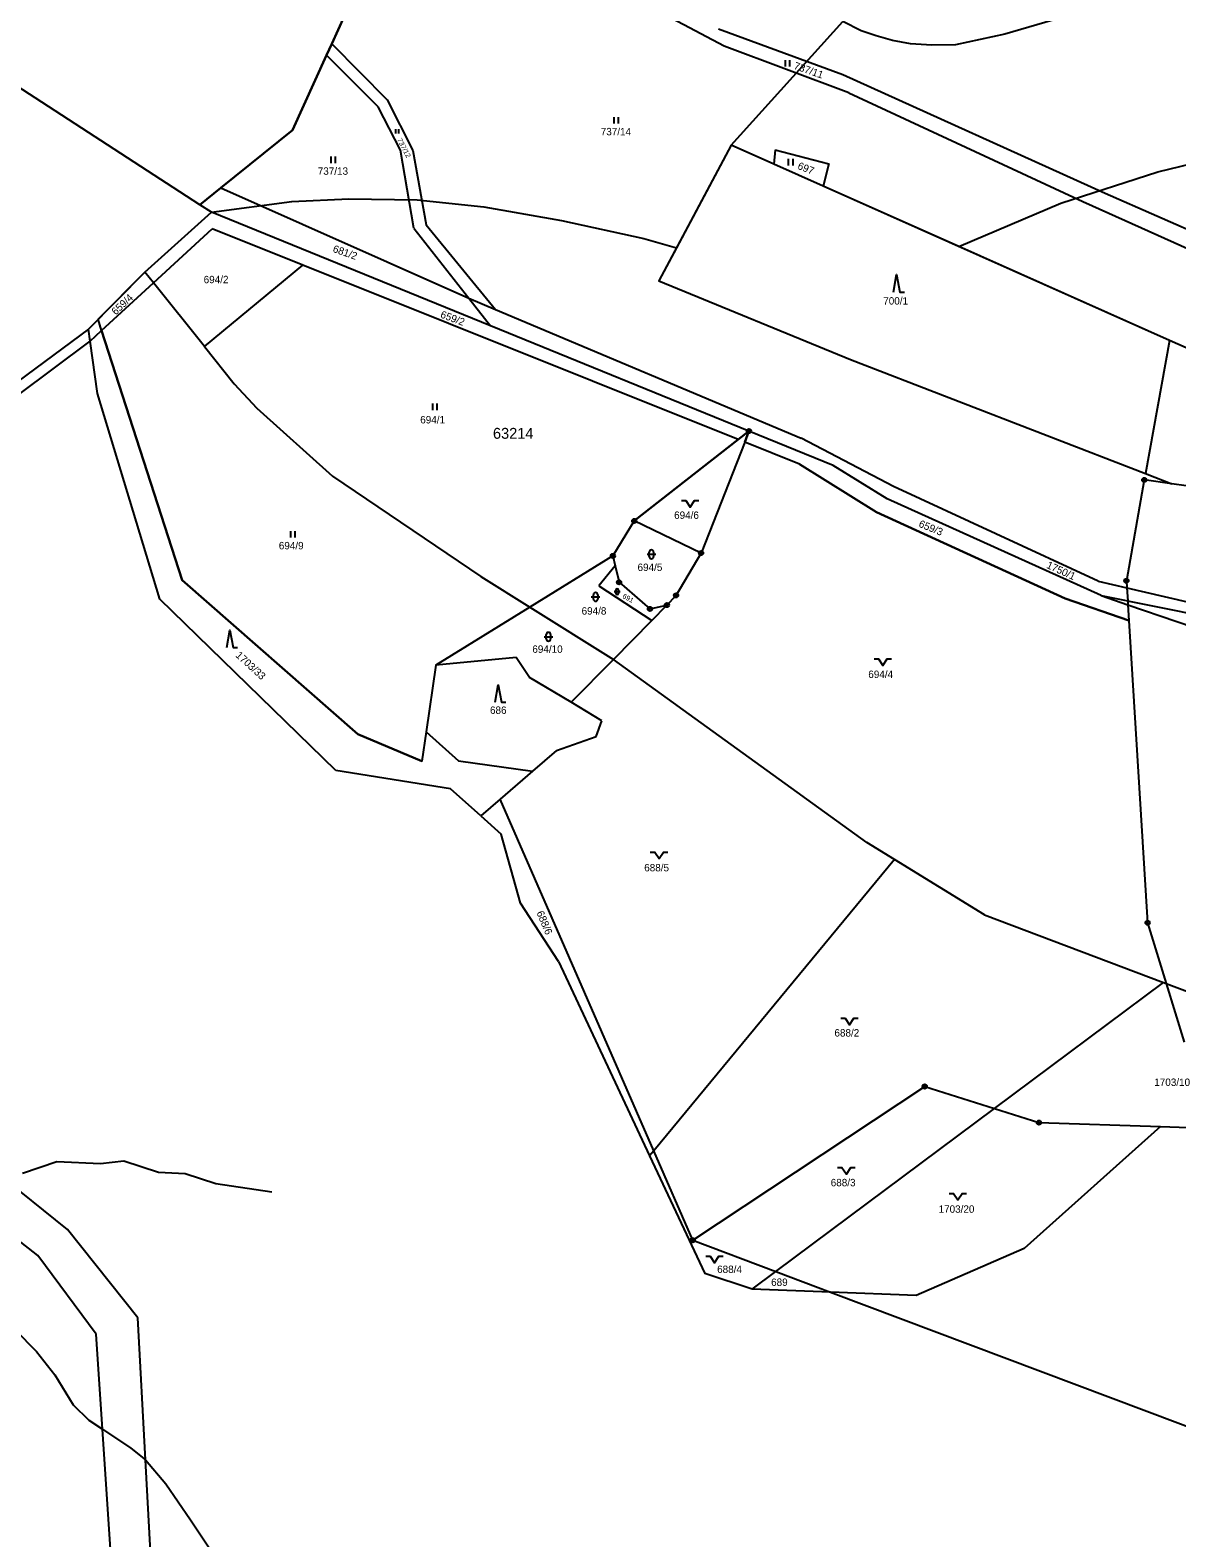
# Model space of a CAD drawing. Extents: x -546762 to -540209, y -1046851 to -1035694.
# Drawn here: x -543953 to -543689.8, y -1042773.8 to -1042427.6 of the extents above; entities that cross this region are included whole.
import ezdxf

# ---------------------------------------------------------------- set-up
doc = ezdxf.new("R2010")
doc.units = 0
for name, color, linetype in [('Vrstva 1', 7, 'Continuous'), ('Vrstva 18', 7, 'Continuous'), ('Vrstva 24', 7, 'Continuous'), ('Vrstva 25', 7, 'Continuous'), ('Vrstva 4', 7, 'Continuous'), ('Vrstva 52', 7, 'Continuous'), ('Vrstva 53', 7, 'Continuous'), ('Vrstva 6', 7, 'Continuous')]:
    doc.layers.add(name, color=color, linetype=linetype)

msp = doc.modelspace()

# ---------------------------------------------------------------- linework, layer by layer
at = {"layer": 'Vrstva 1'}
msp.add_line((-543914, -1042467.7), (-543986.75, -1042420.55), dxfattribs=at)
for points in [[(-543880.86, -1042424.34), (-543883.76, -1042430.75)], [(-543884.95, -1042433.37), (-543892.75, -1042450.56)], [(-543883.76, -1042430.75), (-543884.95, -1042433.37)], [(-543892.75, -1042450.56), (-543909.21, -1042463.84)], [(-543792.12, -1042454.05), (-543808.73, -1042485.17)], [(-543782.33, -1042458.41), (-543792.12, -1042454.05)], [(-543770.99, -1042463.46), (-543782.33, -1042458.41)], [(-543909.21, -1042463.84), (-543914, -1042467.7)], [(-543909.21, -1042463.84), (-543852.31, -1042489.17)], [(-543691.54, -1042498.84), (-543770.99, -1042463.46)], [(-543911.35, -1042469.41), (-543914, -1042467.7)], [(-543926.67, -1042483.2), (-543911.35, -1042469.41)], [(-543847.36, -1042495.5), (-543911.35, -1042469.41)], [(-543924.65, -1042485.6), (-543911.22, -1042473.23)], [(-543890.39, -1042481.58), (-543911.22, -1042473.23)], [(-543912.98, -1042500.25), (-543890.39, -1042481.58)], [(-543790.47, -1042521.6), (-543890.39, -1042481.58)], [(-543939.58, -1042496.26), (-543926.67, -1042483.2)], [(-543936.6, -1042496.61), (-543924.65, -1042485.6)], [(-543912.98, -1042500.25), (-543924.65, -1042485.6)], [(-543808.73, -1042485.17), (-543764.69, -1042503.24)], [(-543852.31, -1042489.17), (-543846.15, -1042491.77)], [(-543852.31, -1042489.17), (-543847.36, -1042495.5)], [(-543846.15, -1042491.77), (-543776.05, -1042521.32)], [(-543939.58, -1042496.26), (-544006.86, -1042546.1)], [(-543788.02, -1042519.68), (-543847.36, -1042495.5)], [(-544013.86, -1042554.81), (-543939.22, -1042499.03)], [(-543939.22, -1042499.03), (-543936.6, -1042496.61)], [(-543936.6, -1042496.61), (-543918.07, -1042553.94)], [(-543691.54, -1042498.84), (-543697.04, -1042529.44)], [(-543643.01, -1042520.26), (-543691.54, -1042498.84)], [(-543764.69, -1042503.24), (-543697.04, -1042529.44)], [(-543790.47, -1042521.6), (-543788.02, -1042519.68)], [(-543788.02, -1042519.68), (-543789, -1042522.19)], [(-543768.69, -1042527.56), (-543788.02, -1042519.68)], [(-543814.33, -1042540.29), (-543790.47, -1042521.6)], [(-543789, -1042522.19), (-543799, -1042547.69)], [(-543776.4, -1042527.24), (-543789, -1042522.19)], [(-543754.86, -1042532.43), (-543776.05, -1042521.32)], [(-543776.4, -1042527.24), (-543758.78, -1042538.26)], [(-543756.29, -1042535.23), (-543768.69, -1042527.56)], [(-543697.3, -1042530.9), (-543701.4, -1042554.03)], [(-543691.01, -1042531.78), (-543697.3, -1042530.9)], [(-543697.04, -1042529.44), (-543691.01, -1042531.78)], [(-543707.88, -1042554.12), (-543754.86, -1042532.43)], [(-543671.28, -1042534.53), (-543691.01, -1042531.78)], [(-543707.2, -1042557.44), (-543756.29, -1042535.23)], [(-543814.33, -1042540.29), (-543819.25, -1042548.35)], [(-543799, -1042547.69), (-543814.33, -1042540.29)], [(-543758.78, -1042538.26), (-543715.46, -1042558.09)], [(-543819.25, -1042548.35), (-543838.28, -1042560.08)], [(-543819.25, -1042548.35), (-543818.71, -1042550.63)], [(-543804.74, -1042557.39), (-543799, -1042547.69)], [(-543818.71, -1042550.63), (-543817.82, -1042554.38)], [(-543918.07, -1042553.94), (-543877.78, -1042589.27)], [(-543817.82, -1042554.38), (-543810.73, -1042560.5)], [(-543707.88, -1042554.12), (-543701.3, -1042555.64)], [(-543701.4, -1042554.03), (-543701.3, -1042555.64)], [(-543806.84, -1042559.61), (-543804.74, -1042557.39)], [(-543715.46, -1042558.09), (-543700.84, -1042563.16)], [(-543707.2, -1042557.44), (-543701.06, -1042559.54)], [(-543707.2, -1042557.44), (-543682.5, -1042562.38)], [(-543701.3, -1042555.64), (-543683.15, -1042559.84)], [(-543838.28, -1042560.08), (-543859.89, -1042573.41)], [(-543810.73, -1042560.5), (-543806.84, -1042559.61)], [(-543810.34, -1042563.16), (-543806.84, -1042559.61)], [(-543701.06, -1042559.54), (-543644.86, -1042578.71)], [(-543701.06, -1042559.54), (-543700.84, -1042563.16)], [(-543819.11, -1042572.08), (-543810.34, -1042563.16)], [(-543700.84, -1042563.16), (-543696.55, -1042632.54)], [(-543841.41, -1042571.65), (-543859.89, -1042573.41)], [(-543838.38, -1042576.23), (-543841.41, -1042571.65)], [(-543828.82, -1042581.95), (-543819.11, -1042572.08)], [(-543760.97, -1042614.11), (-543819.11, -1042572.08)], [(-543859.89, -1042573.41), (-543862.09, -1042588.69)], [(-543828.82, -1042581.95), (-543838.38, -1042576.23)], [(-543821.74, -1042586.18), (-543828.82, -1042581.95)], [(-543823.08, -1042589.77), (-543821.74, -1042586.18)], [(-543877.78, -1042589.27), (-543863.06, -1042595.46)], [(-543862.09, -1042588.69), (-543863.06, -1042595.46)], [(-543832.18, -1042593.02), (-543823.08, -1042589.77)], [(-543832.18, -1042593.02), (-543837.67, -1042597.76)], [(-543837.67, -1042597.76), (-543845.09, -1042604.16)], [(-543845.09, -1042604.16), (-543849.56, -1042608.02)], [(-543809.86, -1042684.9), (-543845.09, -1042604.16)], [(-543849.56, -1042608.02), (-543844.9, -1042612.18)], [(-543840.45, -1042628.07), (-543844.9, -1042612.18)], [(-543754.62, -1042618.03), (-543760.97, -1042614.11)], [(-543754.62, -1042618.03), (-543809.86, -1042684.9)], [(-543734, -1042630.76), (-543754.62, -1042618.03)], [(-543831.74, -1042641.43), (-543840.45, -1042628.07)], [(-543734, -1042630.76), (-543692.88, -1042646.27)], [(-543696.55, -1042632.54), (-543692.29, -1042646.49)], [(-543831.74, -1042641.43), (-543810.83, -1042686.07)], [(-543731.68, -1042675.22), (-543692.88, -1042646.27)], [(-543692.88, -1042646.27), (-543692.29, -1042646.49)], [(-543692.29, -1042646.49), (-543663.02, -1042657.52)], [(-543692.29, -1042646.49), (-543688.16, -1042659.98)], [(-543800.9, -1042705.44), (-543747.67, -1042670.15)], [(-543747.67, -1042670.15), (-543731.68, -1042675.22)], [(-543781.83, -1042712.63), (-543731.68, -1042675.22)], [(-543731.68, -1042675.22), (-543721.47, -1042678.45)], [(-543693.55, -1042679.34), (-543724.87, -1042707.38)], [(-543721.47, -1042678.45), (-543693.55, -1042679.34)], [(-543693.55, -1042679.34), (-543682.85, -1042679.68)], [(-543809.86, -1042684.9), (-543810.83, -1042686.07)], [(-543810.83, -1042686.07), (-543798.17, -1042713.1)], [(-543800.9, -1042705.44), (-543809.86, -1042684.9)], [(-543944.41, -1042703), (-543960.57, -1042690)], [(-543951.18, -1042708.96), (-543973.27, -1042691.69)], [(-543928.23, -1042723.28), (-543944.41, -1042703)], [(-543800.9, -1042705.44), (-543781.83, -1042712.63)], [(-543724.87, -1042707.38), (-543749.65, -1042718.1)], [(-543937.83, -1042726.98), (-543951.18, -1042708.96)], [(-543787.25, -1042716.67), (-543798.17, -1042713.1)], [(-543787.25, -1042716.67), (-543781.83, -1042712.63)], [(-543781.83, -1042712.63), (-543769.3, -1042717.35)], [(-543769.3, -1042717.35), (-543656.9, -1042759.71)], [(-543749.65, -1042718.1), (-543769.3, -1042717.35)], [(-543926.46, -1042755.84), (-543928.23, -1042723.28)], [(-543936.37, -1042748.84), (-543937.83, -1042726.98)], [(-543930.94, -1042830.38), (-543936.37, -1042748.84)], [(-543922.81, -1042823.23), (-543926.46, -1042755.84)]]:
    msp.add_lwpolyline(points, dxfattribs=at)
at = {"layer": 'Vrstva 24'}
for centre, radius in [((-543788.02, -1042519.68), 0.5), ((-543788.02, -1042519.68), 0.1), ((-543697.3, -1042530.9), 0.5), ((-543697.3, -1042530.9), 0.1), ((-543814.33, -1042540.29), 0.5), ((-543814.33, -1042540.29), 0.1), ((-543819.25, -1042548.35), 0.5), ((-543819.25, -1042548.35), 0.1), ((-543799, -1042547.69), 0.5), ((-543799, -1042547.69), 0.1), ((-543817.82, -1042554.38), 0.5), ((-543817.82, -1042554.38), 0.1), ((-543701.4, -1042554.03), 0.5), ((-543701.4, -1042554.03), 0.1), ((-543804.74, -1042557.39), 0.5), ((-543804.74, -1042557.39), 0.1), ((-543810.73, -1042560.5), 0.5), ((-543810.73, -1042560.5), 0.1), ((-543806.84, -1042559.61), 0.5), ((-543806.84, -1042559.61), 0.1), ((-543696.55, -1042632.54), 0.5), ((-543696.55, -1042632.54), 0.1), ((-543747.67, -1042670.15), 0.5), ((-543747.67, -1042670.15), 0.1), ((-543721.47, -1042678.45), 0.5), ((-543721.47, -1042678.45), 0.1), ((-543800.9, -1042705.44), 0.5), ((-543800.9, -1042705.44), 0.1)]:
    msp.add_circle(centre, radius, dxfattribs=at)
at = {"layer": 'Vrstva 25'}
for p, q in [((-543779.63, -1042435.99), (-543779.63, -1042434.49)), ((-543778.63, -1042435.99), (-543778.63, -1042434.49)), ((-543818.94, -1042449.07), (-543818.94, -1042447.57)), ((-543817.94, -1042449.07), (-543817.94, -1042447.57)), ((-543869.02, -1042451.37), (-543869.02, -1042450.36)), ((-543868.34, -1042451.37), (-543868.34, -1042450.36)), ((-543883.88, -1042458.13), (-543883.88, -1042456.63)), ((-543882.88, -1042458.13), (-543882.88, -1042456.63)), ((-543778.91, -1042458.67), (-543778.91, -1042457.17)), ((-543777.91, -1042458.67), (-543777.91, -1042457.17)), ((-543860.53, -1042514.86), (-543860.53, -1042513.36)), ((-543859.53, -1042514.86), (-543859.53, -1042513.36)), ((-543893.16, -1042544.12), (-543893.16, -1042542.62)), ((-543892.16, -1042544.12), (-543892.16, -1042542.62)), ((-543811.41, -1042547.97), (-543809.41, -1042547.97)), ((-543810.91, -1042548.47), (-543810.91, -1042547.47)), ((-543809.91, -1042547.47), (-543809.91, -1042548.47)), ((-543824.22, -1042557.74), (-543822.22, -1042557.74)), ((-543823.72, -1042558.24), (-543823.72, -1042557.24)), ((-543822.72, -1042557.24), (-543822.72, -1042558.24)), ((-543818.92, -1042556.54), (-543817.58, -1042556.54)), ((-543818.58, -1042556.88), (-543818.58, -1042556.21)), ((-543817.92, -1042556.21), (-543817.92, -1042556.88)), ((-543835.02, -1042566.88), (-543833.02, -1042566.88)), ((-543834.52, -1042567.38), (-543834.52, -1042566.38)), ((-543833.52, -1042566.38), (-543833.52, -1042567.38))]:
    msp.add_line(p, q, dxfattribs=at)
for points in [[(-543754.86, -1042487.75), (-543754.16, -1042483.75), (-543753.36, -1042487.75), (-543752.36, -1042487.75)], [(-543803.5, -1042535.63), (-543802.5, -1042535.63), (-543801.5, -1042537.13), (-543800.5, -1042535.63), (-543799.5, -1042535.63)], [(-543907.86, -1042569.35), (-543907.16, -1042565.35), (-543906.36, -1042569.35), (-543905.36, -1042569.35)], [(-543759.28, -1042571.98), (-543758.28, -1042571.98), (-543757.28, -1042573.48), (-543756.28, -1042571.98), (-543755.28, -1042571.98)], [(-543846.29, -1042581.9), (-543845.59, -1042577.9), (-543844.79, -1042581.9), (-543843.79, -1042581.9)], [(-543810.65, -1042616.32), (-543809.65, -1042616.32), (-543808.65, -1042617.82), (-543807.65, -1042616.32), (-543806.65, -1042616.32)], [(-543766.94, -1042654.48), (-543765.94, -1042654.48), (-543764.94, -1042655.98), (-543763.94, -1042654.48), (-543762.94, -1042654.48)], [(-543767.67, -1042688.74), (-543766.67, -1042688.74), (-543765.67, -1042690.24), (-543764.67, -1042688.74), (-543763.67, -1042688.74)], [(-543742.11, -1042694.7), (-543741.11, -1042694.7), (-543740.11, -1042696.2), (-543739.11, -1042694.7), (-543738.11, -1042694.7)], [(-543797.94, -1042709.13), (-543796.94, -1042709.13), (-543795.94, -1042710.63), (-543794.94, -1042709.13), (-543793.94, -1042709.13)]]:
    msp.add_lwpolyline(points, dxfattribs=at)
for centre, radius, start, end in [((-543810.41, -1042547.47), 0.5, 0, 180), ((-543810.41, -1042548.47), 0.5, 180, 0), ((-543823.22, -1042557.24), 0.5, 0, 180), ((-543823.22, -1042558.24), 0.5, 180, 0), ((-543818.25, -1042556.21), 0.335, 0, 180), ((-543818.25, -1042556.88), 0.335, 180, 0), ((-543834.02, -1042566.38), 0.5, 0, 180), ((-543834.02, -1042567.38), 0.5, 180, 0)]:
    msp.add_arc(centre, radius, start, end, dxfattribs=at)
at = {"layer": 'Vrstva 4'}
for points in [[(-543954.69, -1042690.05), (-543946.87, -1042687.34)], [(-543946.87, -1042687.34), (-543936.83, -1042687.84)], [(-543936.83, -1042687.84), (-543931.45, -1042687.23)], [(-543931.45, -1042687.23), (-543923.53, -1042689.82)], [(-543923.53, -1042689.82), (-543917.38, -1042690.11)], [(-543917.38, -1042690.11), (-543910.35, -1042692.42)], [(-543910.35, -1042692.42), (-543897.5, -1042694.37)], [(-543956.37, -1042726.05), (-543951.51, -1042730.98)], [(-543951.51, -1042730.98), (-543947.33, -1042736.38)], [(-543947.33, -1042736.38), (-543943.06, -1042743.26)], [(-543943.06, -1042743.26), (-543939.49, -1042746.78)], [(-543939.49, -1042746.78), (-543936.37, -1042748.84)], [(-543936.37, -1042748.84), (-543929.85, -1042753.16)], [(-543929.85, -1042753.16), (-543926.46, -1042755.84)], [(-543926.46, -1042755.84), (-543921.82, -1042761.37)], [(-543921.82, -1042761.37), (-543916.14, -1042769.65)], [(-543916.14, -1042769.65), (-543910.63, -1042777.9)]]:
    msp.add_lwpolyline(points, dxfattribs=at)
at = {"layer": 'Vrstva 52'}
for points in [[(-543911.35, -1042469.41), (-543914, -1042467.7), (-543909.21, -1042463.84), (-543892.75, -1042450.56), (-543884.95, -1042433.37), (-543883.76, -1042430.75), (-543880.86, -1042424.34), (-543864.22, -1042393.81), (-543874.9, -1042389.04)], [(-543792.12, -1042454.05), (-543766.5, -1042425.67)], [(-543716.49, -1042424.8), (-543729.32, -1042428.56), (-543740.59, -1042430.98), (-543746.09, -1042431.07), (-543750.93, -1042430.79), (-543755.09, -1042430.03), (-543758.82, -1042428.92), (-543762.28, -1042427.75), (-543766.5, -1042425.67)], [(-543739.84, -1042477.33), (-543716.42, -1042467.37), (-543694.17, -1042460.16), (-543673.4, -1042455.07), (-543651.36, -1042451.67), (-543626.13, -1042450.4), (-543604.73, -1042450.61), (-543582.48, -1042451.46), (-543555.56, -1042452.31), (-543534.58, -1042453.58), (-543520.38, -1042453.58), (-543509.36, -1042452.52), (-543500.76, -1042451.67), (-543493.37, -1042450.71), (-543489.01, -1042450.46)], [(-543792.12, -1042454.05), (-543804.68, -1042477.58)], [(-543739.84, -1042477.33), (-543770.99, -1042463.46), (-543782.33, -1042458.41), (-543792.12, -1042454.05)], [(-543911.35, -1042469.41), (-543892.94, -1042466.97), (-543879.86, -1042466.37), (-543864.12, -1042466.61)], [(-543864.12, -1042466.61), (-543848.86, -1042468.18), (-543831.06, -1042471.33), (-543812.16, -1042475.45), (-543804.68, -1042477.58)], [(-543804.68, -1042477.58), (-543808.73, -1042485.17), (-543764.69, -1042503.24), (-543697.04, -1042529.44), (-543691.01, -1042531.78), (-543697.3, -1042530.9), (-543701.4, -1042554.03), (-543701.3, -1042555.64), (-543701.11, -1042558.66), (-543701.06, -1042559.54), (-543700.84, -1042563.16), (-543715.46, -1042558.09), (-543758.78, -1042538.26), (-543776.4, -1042527.24), (-543789, -1042522.19), (-543788.02, -1042519.68), (-543790.47, -1042521.6), (-543814.33, -1042540.29), (-543819.25, -1042548.35), (-543838.28, -1042560.08), (-543859.89, -1042573.41), (-543862.09, -1042588.69), (-543863.06, -1042595.46), (-543877.78, -1042589.27), (-543918.07, -1042553.94), (-543936.6, -1042496.61), (-543937.33, -1042493.98), (-543926.67, -1042483.2), (-543911.35, -1042469.41)], [(-543483.19, -1042553.62), (-543507.43, -1042544.83), (-543550.66, -1042525.64), (-543554.61, -1042523.89), (-543581.39, -1042516.54), (-543608.28, -1042507.31), (-543616.31, -1042504.56), (-543646.85, -1042494.45), (-543645.83, -1042501.33), (-543643.01, -1042520.26), (-543691.54, -1042498.84), (-543739.84, -1042477.33)]]:
    msp.add_lwpolyline(points, dxfattribs=at)
at = {"layer": 'Vrstva 6'}
for points in [[(-543793.69, -1042431.31), (-543819.06, -1042417.83)], [(-543766.5, -1042437.88), (-543795.02, -1042427.4)], [(-543873.12, -1042445.26), (-543884.95, -1042433.37)], [(-543883.76, -1042430.75), (-543871.01, -1042443.64)], [(-543765.12, -1042442), (-543793.69, -1042431.31)], [(-543706.26, -1042465.14), (-543766.5, -1042437.88)], [(-543871.01, -1042443.64), (-543865.12, -1042455.22)], [(-543765.12, -1042442), (-543711.38, -1042467)], [(-543867.99, -1042455.15), (-543873.12, -1042445.26)], [(-543864.91, -1042473.06), (-543867.99, -1042455.15)], [(-543865.12, -1042455.22), (-543862.12, -1042472.29)], [(-543782.03, -1042455.07), (-543782.33, -1042458.41)], [(-543782.03, -1042455.07), (-543769.67, -1042458.34)], [(-543769.67, -1042458.34), (-543770.99, -1042463.46)], [(-543682.57, -1042475.53), (-543706.26, -1042465.14)], [(-543711.38, -1042467), (-543682.95, -1042479.73)], [(-543864.91, -1042473.06), (-543852.31, -1042489.17)], [(-543862.12, -1042472.29), (-543846.15, -1042491.77)], [(-543924.65, -1042485.6), (-543926.67, -1042483.2)], [(-543939.22, -1042499.03), (-543939.58, -1042496.26)], [(-543937.52, -1042511.01), (-543939.22, -1042499.03)], [(-543912.98, -1042500.25), (-543906.14, -1042508.84)], [(-543906.14, -1042508.84), (-543900.92, -1042514.43)], [(-543923.23, -1042558.29), (-543937.52, -1042511.01)], [(-543900.92, -1042514.43), (-543883.55, -1042530)], [(-543883.55, -1042530), (-543849.54, -1042553.03)], [(-543818.71, -1042550.63), (-543822.5, -1042555.24)], [(-543849.54, -1042553.03), (-543838.28, -1042560.08)], [(-543822.5, -1042555.24), (-543810.34, -1042563.16)], [(-543882.8, -1042597.6), (-543923.23, -1042558.29)], [(-543838.28, -1042560.08), (-543819.11, -1042572.08)], [(-543862.09, -1042588.69), (-543854.66, -1042595.38)], [(-543854.66, -1042595.38), (-543837.67, -1042597.76)], [(-543856.53, -1042601.8), (-543882.8, -1042597.6)], [(-543849.56, -1042608.02), (-543856.53, -1042601.8)], [(-543769.3, -1042717.35), (-543787.25, -1042716.67)]]:
    msp.add_lwpolyline(points, dxfattribs=at)

# ---------------------------------------------------------------- texts
at = {"layer": 'Vrstva 18'}
for s, height, rotation, p in [('737/11', 1.7, 340.7715, (-543777.86, -1042436.48)), ('737/12', 1.14, 297.3884, (-543868.77, -1042452.78)), ('697', 1.7, 338.1258, (-543777.01, -1042459.42)), ('681/2', 1.7, 340.609, (-543883.65, -1042478.5)), ('659/4', 1.7, 43.1328, (-543933.33, -1042493.15)), ('659/2', 1.7, 339.6055, (-543858.97, -1042493.56)), ('659/3', 1.7, 337.6997, (-543749.22, -1042541.59)), ('1750/1', 1.7, 335.5483, (-543719.9, -1042551.04)), ('691', 1.14, 331.4346, (-543817.16, -1042557.92)), ('1703/33', 1.7, 317.4692, (-543905.94, -1042571.36)), ('688/6', 1.7, 292.6185, (-543836.8, -1042630.24))]:
    msp.add_text(s, height=height, rotation=rotation, dxfattribs=at).set_placement(p)
for s, p in [('737/14', (-543822.02, -1042451.77)), ('737/13', (-543886.96, -1042460.83)), ('694/2', (-543913.14, -1042485.73)), ('700/1', (-543757.2, -1042490.63)), ('694/1', (-543863.45, -1042517.92)), ('694/6', (-543805.19, -1042539.83)), ('694/9', (-543895.9, -1042546.82)), ('694/5', (-543813.58, -1042551.79)), ('694/8', (-543826.42, -1042561.81)), ('694/10', (-543837.72, -1042570.58)), ('694/4', (-543760.63, -1042576.36)), ('686', (-543847.44, -1042584.6)), ('688/5', (-543812.05, -1042620.76)), ('688/2', (-543768.4, -1042658.68)), ('1703/10', (-543695.01, -1042670.02)), ('688/3', (-543769.25, -1042693.06)), ('1703/20', (-543744.5, -1042699.14)), ('688/4', (-543795.32, -1042712.97)), ('689', (-543782.93, -1042715.93))]:
    msp.add_text(s, height=1.7, dxfattribs=at).set_placement(p)
at = {"layer": 'Vrstva 53'}
msp.add_text('63214', height=2.5, dxfattribs=at).set_placement((-543846.76, -1042521.44))

doc.saveas('drawing.dxf')
